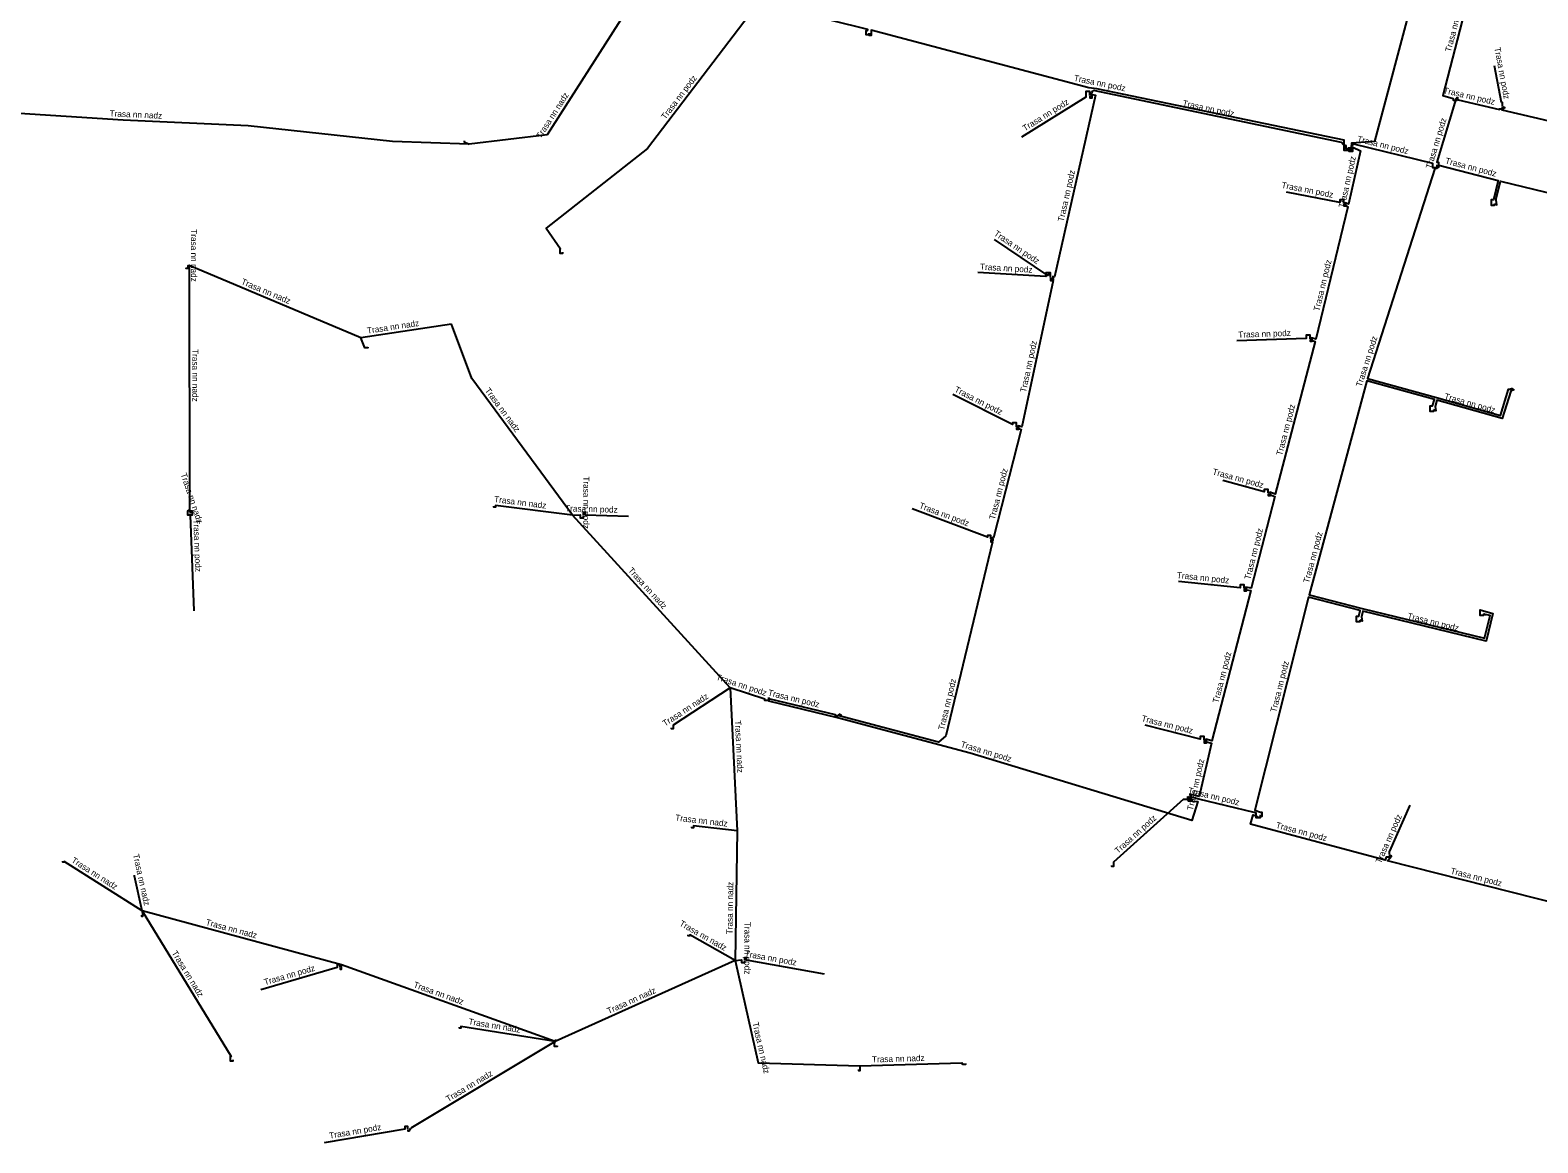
# Model space of a CAD drawing. Extents: x -742082 to -717476, y -1040737 to -1024597.
# Drawn here: x -736008 to -735762.9, y -1032106.6 to -1031925.7 of the extents above; entities that cross this region are included whole.
import ezdxf

# ---------------------------------------------------------------- set-up
doc = ezdxf.new("R2010")
doc.units = 0
for name, color, linetype in [('Level 13', 7, 'Continuous'), ('Level 14', 7, 'Continuous'), ('Level 15', 7, 'Continuous'), ('Level 20', 7, 'Continuous')]:
    doc.layers.add(name, color=color, linetype=linetype)

msp = doc.modelspace()

# ---------------------------------------------------------------- linework, layer by layer
at = {"layer": 'Level 13'}
for p, q in [((-735954.2, -1031975.7), (-735982.15, -1031963.95)), ((-735939.5, -1031973.5), (-735954.2, -1031975.7)), ((-735894.17, -1032032.59), (-735919.79, -1032004.53)), ((-735894.17, -1032032.59), (-735893.03, -1032055.88)), ((-735893.03, -1032055.88), (-735893.36, -1032076.97)), ((-735957.37, -1032077.65), (-735989.78, -1032068.89)), ((-735922.63, -1032090.13), (-735957.37, -1032077.65)), ((-735893.36, -1032076.97), (-735922.63, -1032090.13)), ((-735873.1, -1032094.1), (-735856.5, -1032093.6))]:
    msp.add_line(p, q, dxfattribs=at)
for points in [[(-735937.4, -1031943.7), (-735937.4, -1031943.86), (-735936.6, -1031944.2)], [(-735982.15, -1031963.95), (-735982.34, -1031964), (-735982.34, -1031964.46), (-735982.6, -1031964.46), (-735982.6, -1031964.3)], [(-735919.79, -1032004.53), (-735936.2, -1031982.3), (-735939.5, -1031973.5)], [(-735953.1, -1031977.2), (-735953.1, -1031977.36), (-735953.55, -1031977.36), (-735954.2, -1031975.7)], [(-735981.9, -1032004.4), (-735981.9, -1032004.56), (-735982.35, -1032004.56), (-735982.35, -1032003.85), (-735982.1, -1032003.7)], [(-735989.9, -1032069.6), (-735989.9, -1032069.76), (-735989.64, -1032069.76), (-735989.64, -1032069.3), (-735989.78, -1032068.89)], [(-735957.6, -1032078.2), (-735957.6, -1032078.36), (-735957.34, -1032078.36), (-735957.34, -1032077.86), (-735957.37, -1032077.65)], [(-735893.36, -1032076.97), (-735889.6, -1032093.6), (-735873.1, -1032094.1)], [(-735922.3, -1032090.8), (-735922.3, -1032090.96), (-735922.76, -1032090.96), (-735922.76, -1032090.45), (-735922.63, -1032090.13)], [(-735922.6, -1032089.8), (-735922.6, -1032089.97), (-735922.63, -1032090.13)], [(-735873.3, -1032094.7), (-735873.3, -1032094.86), (-735873.05, -1032094.86), (-735873.05, -1032094.31), (-735873.1, -1032094.1)], [(-735855.9, -1032093.7), (-735855.9, -1032093.86), (-735856.35, -1032093.86), (-735856.5, -1032093.6)], [(-735946.6, -1032104.5), (-735946.6, -1032104.66), (-735946.34, -1032104.66), (-735946.12, -1032104.22)]]:
    msp.add_lwpolyline(points, dxfattribs=at)
at = {"layer": 'Level 14'}
for p, q in [((-735982.15, -1031963.95), (-735982.1, -1032003.7)), ((-735982.1, -1032003.7), (-735981.9, -1032004.29)), ((-735922.63, -1032090.13), (-735946.12, -1032104.22))]:
    msp.add_line(p, q, dxfattribs=at)
for points in [[(-735911.5, -1031923.3), (-735923.93, -1031942.72), (-735936.6, -1031944.2)], [(-735936.6, -1031944.2), (-735949.1, -1031943.8), (-735972.53, -1031941.22), (-735992.89, -1031940.3), (-736020.74, -1031938.5), (-736041.1, -1031936.8)], [(-735919.79, -1032004.53), (-735932.34, -1032002.95), (-735932.34, -1032003.26), (-735932.6, -1032003.26), (-735932.6, -1032003.1)], [(-735894.17, -1032032.59), (-735903.45, -1032038.67), (-735903.45, -1032039.26), (-735903.7, -1032039.26), (-735903.7, -1032039.1)], [(-735893.03, -1032055.88), (-735900.15, -1032055.04), (-735900.15, -1032055.36), (-735900.4, -1032055.36), (-735900.4, -1032055.2)], [(-735989.78, -1032068.89), (-736002.44, -1032060.83), (-736002.44, -1032060.96), (-736002.7, -1032060.96), (-736002.7, -1032060.8)], [(-735989.78, -1032068.89), (-735991.02, -1032063.26), (-735991, -1032063.26), (-735991, -1032063.1)], [(-735989.78, -1032068.89), (-735975.31, -1032092.55), (-735975.45, -1032092.55), (-735975.45, -1032093.26), (-735975, -1032093.26), (-735975, -1032093.1)], [(-735893.36, -1032076.97), (-735900.74, -1032072.8), (-735900.74, -1032072.96), (-735901, -1032072.96), (-735901, -1032072.8)], [(-735922.63, -1032090.13), (-735937.94, -1032087.66), (-735937.94, -1032087.96), (-735938.2, -1032087.96), (-735938.2, -1032087.8)]]:
    msp.add_lwpolyline(points, dxfattribs=at)
at = {"layer": 'Level 15'}
for points in [[(-735765.68, -1031847.78), (-735765.68, -1031848.39), (-735764.06, -1031848.58), (-735789.4, -1031943.8), (-735793.14, -1031944.05), (-735793.14, -1031945.16), (-735793.56, -1031945.16), (-735793.56, -1031944.69)], [(-735770.7, -1031908.7), (-735770.15, -1031909.06), (-735771.24, -1031909.06), (-735778.3, -1031936.3), (-735776.65, -1031936.77), (-735776.65, -1031937.06), (-735775.99, -1031937.06), (-735775.99, -1031936.59)], [(-735871.54, -1031926.19), (-735871.54, -1031926.46), (-735872.05, -1031926.46), (-735872.05, -1031925.75), (-735871.83, -1031925.75), (-735871.79, -1031925.55), (-735889.5, -1031921.2), (-735907.6, -1031944.9), (-735924.1, -1031957.9), (-735921.75, -1031961.25), (-735921.85, -1031961.25), (-735921.85, -1031961.96), (-735921.4, -1031961.96), (-735921.4, -1031961.8)], [(-735793.58, -1031944.69), (-735793.58, -1031945.26), (-735794.35, -1031945.26), (-735794.35, -1031943.59), (-735834.56, -1031935.2), (-735835.84, -1031935.07), (-735871.24, -1031925.7), (-735871.24, -1031926.56), (-735871.57, -1031926.56), (-735871.57, -1031926.19)], [(-735768.6, -1031937.99), (-735768.6, -1031937.45), (-735768.78, -1031937.45), (-735769.9, -1031931.5)], [(-735835.7, -1031936.29), (-735835.7, -1031935.65), (-735836.35, -1031935.65), (-735836.35, -1031936.55), (-735846.8, -1031943.1)], [(-735793.51, -1031944.69), (-735793.51, -1031944.96), (-735794.05, -1031944.96), (-735794.05, -1031944.48), (-735794.46, -1031944.35), (-735794.81, -1031943.94), (-735835.11, -1031935.5), (-735835.29, -1031935.61), (-735835.45, -1031935.85), (-735835.35, -1031936.56), (-735835.7, -1031936.4)], [(-735835.7, -1031936.4), (-735835.7, -1031936.66), (-735835.34, -1031936.66), (-735835.34, -1031936.14), (-735834.79, -1031936.26), (-735841.46, -1031965.81), (-735841.74, -1031965.72), (-735841.65, -1031966.26), (-735842.1, -1031966)], [(-735775.94, -1031936.59), (-735775.94, -1031936.86), (-735776.19, -1031936.86), (-735776.2, -1031936.9), (-735779.29, -1031947.15), (-735779.04, -1031947.15), (-735779.04, -1031947.86), (-735779.22, -1031947.86), (-735779.22, -1031947.59)], [(-735775.97, -1031936.59), (-735775.97, -1031936.96), (-735775.8, -1031936.96), (-735775.81, -1031936.99), (-735769.09, -1031938.56), (-735769.07, -1031938.46), (-735768.6, -1031938.46), (-735768.6, -1031938.1)], [(-735768.6, -1031938.1), (-735768.25, -1031938.26), (-735768.68, -1031938.56), (-735768.7, -1031938.65), (-735743.25, -1031944.59), (-735743.25, -1031944.76), (-735742.6, -1031944.76), (-735742.6, -1031944.4)], [(-735793.6, -1031944.69), (-735793.6, -1031945.36), (-735792.94, -1031945.36), (-735792.94, -1031944.69), (-735791.7, -1031945.3), (-735793.66, -1031954), (-735794.15, -1031953.75), (-735794.15, -1031954.16), (-735794.4, -1031954)], [(-735779.27, -1031947.59), (-735779.27, -1031948.06), (-735779.95, -1031948.06), (-735779.95, -1031947.36), (-735792.78, -1031944.21), (-735793.24, -1031944.48), (-735793.24, -1031945.06), (-735793.53, -1031945.06), (-735793.53, -1031944.69)], [(-735779.29, -1031947.59), (-735779.29, -1031948.16), (-735779.61, -1031948.16), (-735790.54, -1031982.31), (-735779.35, -1031985.41), (-735768.93, -1031988.35), (-735767.62, -1031984.06), (-735767.2, -1031984.06), (-735767.2, -1031983.9)], [(-735779.24, -1031947.59), (-735779.24, -1031947.96), (-735778.94, -1031947.96), (-735778.94, -1031947.62), (-735769.29, -1031950.15), (-735770.09, -1031953.25), (-735770.45, -1031953.25), (-735770.45, -1031954.16), (-735769.9, -1031954.16), (-735769.9, -1031953.9)], [(-735769.9, -1031953.9), (-735769.55, -1031954.06), (-735769.65, -1031953.35), (-735769.7, -1031953.35), (-735768.91, -1031950.25), (-735721.59, -1031961.75), (-735721.8, -1031962.65), (-735722.15, -1031962.65), (-735722.15, -1031963.56), (-735721.6, -1031963.56), (-735721.6, -1031963.3)], [(-735794.4, -1031953.89), (-735794.4, -1031953.25), (-735795.05, -1031953.25), (-735795.05, -1031953.69), (-735803.7, -1031952)], [(-735794.4, -1031954), (-735794.4, -1031954.26), (-735794.05, -1031954.26), (-735794.05, -1031954.25), (-735793.75, -1031954.4), (-735798.95, -1031975.91), (-735799.65, -1031975.7), (-735799.55, -1031976.16), (-735799.9, -1031976)], [(-735842.09, -1031965.89), (-735842.09, -1031965.45), (-735842.55, -1031965.45), (-735842.55, -1031965.56), (-735851.2, -1031959.7)], [(-735842.11, -1031965.89), (-735842.11, -1031965.15), (-735842.85, -1031965.15), (-735842.85, -1031965.76), (-735853.9, -1031965.1)], [(-735842.1, -1031966), (-735842.1, -1031966.36), (-735841.64, -1031966.36), (-735846.76, -1031990.2), (-735847.34, -1031990.01), (-735847.25, -1031990.46), (-735847.6, -1031990.3)], [(-735799.9, -1031975.89), (-735799.9, -1031975.25), (-735800.55, -1031975.25), (-735800.55, -1031975.82), (-735811.8, -1031976.2)], [(-735799.9, -1031976), (-735799.9, -1031976.26), (-735799.55, -1031976.26), (-735799.55, -1031976.15), (-735799.05, -1031976.29), (-735805.55, -1032001.11), (-735806.45, -1032000.81), (-735806.35, -1032001.26), (-735806.7, -1032001.1)], [(-735847.6, -1031990.19), (-735847.6, -1031989.55), (-735848.25, -1031989.55), (-735848.25, -1031989.82), (-735858, -1031984.9)], [(-735779.8, -1031987.4), (-735779.8, -1031987.66), (-735780.35, -1031987.66), (-735780.35, -1031986.75), (-735779.97, -1031986.75), (-735779.65, -1031985.74), (-735790.65, -1031982.69), (-735800.05, -1032017.51), (-735791.45, -1032019.71), (-735771.55, -1032024.56), (-735770.64, -1032020.85), (-735771.45, -1032020.68), (-735771.35, -1032020.76), (-735771.7, -1032020.6)], [(-735767.2, -1031983.9), (-735766.75, -1031984.16), (-735767.28, -1031984.38), (-735768.67, -1031988.85), (-735779.27, -1031985.84), (-735779.58, -1031986.85), (-735779.55, -1031986.85), (-735779.45, -1031987.56), (-735779.8, -1031987.4)], [(-735847.6, -1031990.3), (-735847.6, -1031990.56), (-735847.24, -1031990.56), (-735847.24, -1031990.46), (-735846.85, -1031990.59), (-735851.35, -1032008.21), (-735851.55, -1032008.17), (-735851.45, -1032008.66), (-735851.8, -1032008.5)], [(-735806.7, -1032000.99), (-735806.7, -1032000.35), (-735807.35, -1032000.35), (-735807.35, -1032000.75), (-735814.1, -1031998.9)], [(-735806.7, -1032001.1), (-735806.7, -1032001.36), (-735806.34, -1032001.36), (-735806.34, -1032001.26), (-735805.65, -1032001.49), (-735809.45, -1032016.41), (-735810.34, -1032016.26), (-735810.25, -1032016.76), (-735810.6, -1032016.6)], [(-735982.1, -1032003.7), (-735982, -1032003.85), (-735981.65, -1032003.85), (-735981.65, -1032004.56), (-735981.99, -1032004.56), (-735981.4, -1032020.1)], [(-735919.79, -1032004.53), (-735918.55, -1032004.51), (-735918.55, -1032004.96), (-735918, -1032004.96), (-735918, -1032004.7)], [(-735918, -1032004.59), (-735918, -1032004.15), (-735917.74, -1032004.15), (-735917.74, -1032004.51), (-735910.7, -1032004.7)], [(-735851.8, -1032008.39), (-735851.8, -1032007.85), (-735852.35, -1032007.85), (-735852.35, -1032008.13), (-735864.6, -1032003.5)], [(-735851.8, -1032008.5), (-735851.8, -1032008.86), (-735851.51, -1032008.86), (-735859.1, -1032040.4), (-735860.32, -1032041.44), (-735876.47, -1032037.15), (-735876.15, -1032037.06), (-735876.5, -1032036.9)], [(-735810.6, -1032016.49), (-735810.6, -1032015.85), (-735811.25, -1032015.85), (-735811.25, -1032016.34), (-735821.3, -1032015.3)], [(-735810.6, -1032016.6), (-735810.6, -1032016.86), (-735810.24, -1032016.86), (-735810.24, -1032016.68), (-735809.55, -1032016.79), (-735815.85, -1032041.21), (-735816.84, -1032040.98), (-735816.75, -1032041.46), (-735817.1, -1032041.3)], [(-735791.8, -1032021.6), (-735791.8, -1032021.86), (-735792.35, -1032021.86), (-735792.35, -1032020.95), (-735791.99, -1032020.95), (-735791.74, -1032020.04), (-735800.15, -1032017.89), (-735808.9, -1032052.51), (-735807.98, -1032052.85), (-735807.74, -1032052.85), (-735807.74, -1032053.56), (-735807.94, -1032053.56), (-735807.94, -1032053.29)], [(-735771.7, -1032020.6), (-735771.7, -1032020.86), (-735772.25, -1032020.86), (-735772.25, -1032019.95), (-735770.16, -1032020.55), (-735771.25, -1032025.04), (-735791.32, -1032020.13), (-735791.56, -1032021.05), (-735791.55, -1032021.05), (-735791.45, -1032021.76), (-735791.8, -1032021.6)], [(-735887.89, -1032034.19), (-735887.89, -1032034.66), (-735888.55, -1032034.66), (-735888.55, -1032034.45), (-735894.17, -1032032.59)], [(-735819.74, -1032050.29), (-735819.74, -1032050.97), (-735818.12, -1032051.08), (-735819.1, -1032054.2), (-735855.18, -1032043.22), (-735876.75, -1032037.49), (-735887.87, -1032034.76), (-735887.87, -1032034.19)], [(-735876.5, -1032036.9), (-735876.5, -1032037.16), (-735877.05, -1032037.16), (-735877.05, -1032037.01), (-735887.66, -1032034.46), (-735887.84, -1032034.46), (-735887.84, -1032034.19)], [(-735817.1, -1032041.19), (-735817.1, -1032040.55), (-735817.75, -1032040.55), (-735817.75, -1032040.96), (-735826.7, -1032038.7)], [(-735817.1, -1032041.3), (-735817.1, -1032041.56), (-735816.74, -1032041.56), (-735816.74, -1032041.41), (-735815.94, -1032041.59), (-735817.91, -1032050.31), (-735819.44, -1032049.91), (-735819.31, -1032050.66), (-735819.77, -1032050.29)], [(-735819.77, -1032050.29), (-735819.77, -1032050.76), (-735820.45, -1032050.76), (-735820.45, -1032050.7), (-735831.84, -1032060.98), (-735831.84, -1032061.66), (-735832.1, -1032061.66), (-735832.1, -1032061.5)], [(-735807.99, -1032053.29), (-735807.99, -1032053.76), (-735808.65, -1032053.76), (-735808.65, -1032053.02), (-735809, -1032052.9), (-735818, -1032050.7), (-735819.24, -1032050.37), (-735819.24, -1032050.86), (-735819.79, -1032050.86), (-735819.79, -1032050.29)], [(-735787, -1032059.8), (-735787, -1032060.16), (-735787.52, -1032060.16), (-735787.69, -1032060.65), (-735809.6, -1032054.8), (-735809.12, -1032053.28), (-735808.55, -1032053.47), (-735808.55, -1032053.66), (-735807.97, -1032053.66), (-735807.97, -1032053.29)], [(-735787, -1032059.69), (-735787, -1032059.15), (-735786.9, -1032059.15), (-735783.6, -1032051.7)], [(-735754.3, -1032068.1), (-735754.3, -1032068.46), (-735754.82, -1032068.46), (-735754.99, -1032068.95), (-735787.31, -1032060.75), (-735786.65, -1032059.96), (-735787, -1032059.8)], [(-735957.6, -1032078.09), (-735957.6, -1032077.65), (-735958.05, -1032077.65), (-735958.05, -1032078.1), (-735970.5, -1032081.7)], [(-735893.36, -1032076.97), (-735892.35, -1032076.85), (-735892.35, -1032077.26), (-735891.8, -1032077.26), (-735891.8, -1032077)], [(-735891.8, -1032076.89), (-735891.8, -1032076.45), (-735891.55, -1032076.45), (-735891.55, -1032076.86), (-735878.9, -1032079.1)], [(-735946.6, -1032104.39), (-735946.6, -1032103.95), (-735947.05, -1032103.95), (-735947.05, -1032104.36), (-735960.2, -1032106.6)]]:
    msp.add_lwpolyline(points, dxfattribs=at)

# ---------------------------------------------------------------- texts
at = {"layer": 'Level 20'}
for s, rotation, p in [('Trasa nn podz', 75.4798, (-735777, -1031929.3)), ('Trasa nn podz', 280.6197, (-735769.94, -1031928.56)), ('Trasa nn podz', 52.6306, (-735904.7, -1031940.28)), ('Trasa nn podz', 348.2162, (-735838.36, -1031933.9)), ('Trasa nn nadz', 57.3782, (-735924.96, -1031943.41)), ('Trasa nn podz', 346.8911, (-735778.29, -1031935.9)), ('Trasa nn podz', 32.0989, (-735846.24, -1031942.16)), ('Trasa nn podz', 348.1735, (-735820.69, -1031938.01)), ('Trasa nn nadz', 357.4128, (-735995.09, -1031939.7)), ('Trasa nn podz', 73.2018, (-735780.16, -1031948.3)), ('Trasa nn podz', 346.2012, (-735792.31, -1031943.81)), ('Trasa nn podz', 77.3351, (-735794.31, -1031954.64)), ('Trasa nn podz', 345.3111, (-735778, -1031947.35)), ('Trasa nn podz', 77.2851, (-735839.96, -1031956.89)), ('Trasa nn podz', 348.9299, (-735804.6, -1031951.31)), ('Trasa nn nadz', 270, (-735981.84, -1031958.05)), ('Trasa nn podz', 325.8716, (-735851.38, -1031958.98)), ('Trasa nn podz', 76.3954, (-735798.39, -1031971.45)), ('Trasa nn podz', 356.5761, (-735853.58, -1031964.62)), ('Trasa nn nadz', 337.1984, (-735973.78, -1031966.93)), ('Trasa nn nadz', 8.5117, (-735953.14, -1031975.04)), ('Trasa nn podz', 1.9416, (-735811.55, -1031975.69)), ('Trasa nn nadz', 270.0721, (-735981.63, -1031977.54)), ('Trasa nn podz', 77.8937, (-735846.08, -1031984.64)), ('Trasa nn podz', 72.2553, (-735791.52, -1031983.75)), ('Trasa nn nadz', 306.4344, (-735934.12, -1031984.28)), ('Trasa nn podz', 333.213, (-735857.81, -1031984.43)), ('Trasa nn podz', 344.1975, (-735778.16, -1031985.64)), ('Trasa nn podz', 75.3235, (-735804.45, -1031994.92)), ('Trasa nn podz', 75.6644, (-735851.14, -1032005.35)), ('Trasa nn podz', 344.6785, (-735815.84, -1031997.9)), ('Trasa nn nadz', 288.6889, (-735983.54, -1031997.88)), ('Trasa nn podz', 270, (-735918.05, -1031998.23)), ('Trasa nn nadz', 352.8041, (-735932.6, -1032002.41)), ('Trasa nn podz', 358.452, (-735921.02, -1032003.92)), ('Trasa nn podz', 339.2957, (-735863.54, -1032003.37)), ('Trasa nn podz', 272.161, (-735981.46, -1032005.24)), ('Trasa nn podz', 75.6996, (-735809.63, -1032015.09)), ('Trasa nn podz', 74.8965, (-735800.07, -1032015.66)), ('Trasa nn nadz', 312.3974, (-735910.85, -1032013.58)), ('Trasa nn podz', 354.0753, (-735821.59, -1032014.77)), ('Trasa nn podz', 346.2507, (-735784.14, -1032021.37)), ('Trasa nn podz', 75.5298, (-735814.8, -1032035.16)), ('Trasa nn podz', 75.8106, (-735805.41, -1032036.67)), ('Trasa nn podz', 341.6783, (-735896.54, -1032031.28)), ('Trasa nn podz', 76.4704, (-735859.41, -1032039.57)), ('Trasa nn nadz', 33.2347, (-735904.76, -1032038.93)), ('Trasa nn podz', 346.4669, (-735888.1, -1032033.84)), ('Trasa nn nadz', 272.8023, (-735893.41, -1032037.93)), ('Trasa nn podz', 345.8219, (-735827.37, -1032038.01)), ('Trasa nn podz', 343.0725, (-735856.77, -1032042.21)), ('Trasa nn podz', 77.2759, (-735818.95, -1032052.63)), ('Trasa nn podz', 346.2637, (-735819.81, -1032049.74)), ('Trasa nn nadz', 353.2815, (-735903.14, -1032054.19)), ('Trasa nn podz', 42.0645, (-735831.11, -1032059.64)), ('Trasa nn podz', 66.1049, (-735788.38, -1032061.26)), ('Trasa nn podz', 345.0525, (-735805.53, -1032055.37)), ('Trasa nn nadz', 327.5146, (-736001.38, -1032060.91)), ('Trasa nn nadz', 282.4274, (-735991.28, -1032059.74)), ('Trasa nn podz', 345.7578, (-735777.13, -1032062.82)), ('Trasa nn nadz', 89.1036, (-735893.79, -1032072.7)), ('Trasa nn nadz', 344.8751, (-735979.51, -1032071.15)), ('Trasa nn nadz', 330.5509, (-735902.53, -1032071.22)), ('Trasa nn podz', 270, (-735891.85, -1032070.66)), ('Trasa nn nadz', 301.4421, (-735985.02, -1032075.72)), ('Trasa nn podz', 349.967, (-735891.87, -1032076.3)), ('Trasa nn podz', 16.1225, (-735969.81, -1032080.98)), ('Trasa nn nadz', 340.2397, (-735945.75, -1032081.29)), ('Trasa nn nadz', 24.209, (-735913.93, -1032085.67)), ('Trasa nn nadz', 350.8286, (-735936.77, -1032087.34)), ('Trasa nn nadz', 282.7402, (-735890.56, -1032087.09)), ('Trasa nn nadz', 1.7253, (-735871.1, -1032093.54)), ('Trasa nn nadz', 30.9566, (-735940.02, -1032099.98)), ('Trasa nn podz', 9.6687, (-735959.27, -1032105.93))]:
    msp.add_text(s, height=1, rotation=rotation, dxfattribs=at).set_placement(p)

doc.saveas('drawing.dxf')
